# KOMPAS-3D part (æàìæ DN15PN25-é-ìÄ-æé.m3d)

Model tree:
1. Объединить компоненты:1  (labels: СЕНС DN15PN25-В-НО)
2. Эскиз:1
3. Операция выдавливания:1
     Расстояние 1 = 14
4. Фаска:1
     Угол = 45; Длина 1 = 2; Длина 2 = 2

Referenced files in D:\Савин\!СЕНСОР\3D для заказчика\!Новый перечень\СЕНС\6. СЕНС-В-НО\DN15\: СЕНС DN15PN25-В-НО.a3d
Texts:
  СЕНС DN15PN25-В-НО-СВ
  ООО НПП Сенсор
  СЕНС DN15PN25-В-НО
